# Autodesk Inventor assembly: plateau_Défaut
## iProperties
Shininess: 64.0
Length Units: 11269
Angle Units: 11279
Time Units: 11290
Mass Units: 11283
Length Display Precision: 3
Angle Display Precision: 2
Compacted: True
Created: 2006-11
Part Number: plateau_Défaut
Document SubType Name: Assembly
Designer: profs_sti
Density: 0.0
Volumn: 0.0
Area: 0.0
PropertySet Name: Model Information
Control State: 0
Master: False
Checked Out: False
Author: profs_sti
